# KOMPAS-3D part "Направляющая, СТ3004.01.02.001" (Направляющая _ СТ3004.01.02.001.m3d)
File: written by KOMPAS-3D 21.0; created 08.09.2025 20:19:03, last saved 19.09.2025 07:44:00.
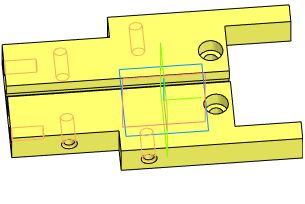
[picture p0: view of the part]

Document properties: Полное имя файла: C:\Users\Lutik\Yandex.Disk\Документы\Новая папка\Стапель №2\Стапель _ СТ3004.00.00.000\Опора _ СТ3004.01.00.000\3D\Кронштейн _ СТ3004.01.02.000\Направляющая _ СТ3004.01.02.001.m3d

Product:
- Part/product: Направляющая  | designation СТ3004.01.02.001
    Материал: Сталь 45  ГОСТ 1050-2013 (density 7810 kg/m3)
    Масса: 1.713262
    Форматы листов документа: A3

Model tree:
1. Эскиз:1
2. Элемент выдавливания:1
     Расстояние 1 = 80; Расстояние 2 = 95
3. Эскиз:2  (with: Элемент выдавливания:1)
4. Элемент выдавливания:2
     Расстояние 2 = 20
5. Эскиз:3  (with: Элемент выдавливания:1)
6. Элемент выдавливания:3
     Расстояние 2 = 20
7. Эскиз:4  (with: Элемент выдавливания:1, Элемент выдавливания:3)
8. Элемент выдавливания:4
     Расстояние 2 = 10
9. Эскиз:6  (with: Элемент выдавливания:1)
10. ЛСК:2  (with: Плоскость XY, Плоскость ZX, Плоскость ZY, Ось X, Ось Y, Ось Z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)
     Ось X. Y = -1; Ось Y. X = 1; Ось Z. Z = 1; Координата X = 25; Координата Y = -95; Координата Z = 10; Точка начала. Х = 25; Точка начала. Y = -95; Точка начала. Z = 10
11. Эскиз:7
12. Элемент вращения:1
     Угол 1 = 360
13. Смещенная плоскость:1  (with: Элемент выдавливания:1)
     Расстояние = 0.923418
14. Условное изображение резьбы:1  (with: Элемент вращения:1)  (labels: 8x1,25)
     Длина резьбы = 19.0766; Шаг резьбы = 1.25; Номинальный диаметр резьбы = 8
15. Подгонка:1
16. Отверстие М8x20/1,6x45°
17. Эскиз:9  (with: Элемент выдавливания:1)
18. ЛСК:4  (with: Плоскость XY, Плоскость ZX, Плоскость ZY, Ось X, Ось Y, Ось Z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)
     Ось X. Y = -1; Ось Y. X = 1; Ось Z. Z = 1; Координата X = -25; Координата Y = -95; Координата Z = 10; Точка начала. Х = -25; Точка начала. Y = -95; Точка начала. Z = 10
19. Эскиз:10
20. Элемент вращения:2
     Угол 1 = 360
21. Смещенная плоскость:2  (with: Элемент выдавливания:1)
     Расстояние = 0.923418
22. Условное изображение резьбы:2  (with: Элемент вращения:2)  (labels: 8x1,25)
     Длина резьбы = 19.0766; Шаг резьбы = 1.25; Номинальный диаметр резьбы = 8
23. Подгонка:2
24. Отверстие М8x20/1,6x45° (1)
25. Эскиз:28  (with: Элемент выдавливания:2)
26. ЛСК:18  (with: Плоскость XY, Плоскость ZX, Плоскость ZY, Ось X, Ось Y, Ось Z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)
     Ось X. X = 1; Ось Y. Y = 1; Ось Z. Z = 1; Координата X = 35; Координата Y = -60; Координата Z = 10; Точка начала. Х = 35; Точка начала. Y = -60; Точка начала. Z = 10
27. Эскиз:29
28. Элемент вращения:7
     Угол 1 = 360
29. Смещенная плоскость:7  (with: Элемент выдавливания:2)
     Расстояние = 0.923418
30. Условное изображение резьбы:7  (with: Элемент вращения:7, Подгонка:1)  (labels: 8x1,25)
     Длина резьбы = 19.0766; Шаг резьбы = 1.25; Номинальный диаметр резьбы = 8
31. Отверстие М8x20/1,6x45° (2)
32. Эскиз:32  (with: Элемент выдавливания:2)
33. ЛСК:21  (with: Плоскость XY, Плоскость ZX, Плоскость ZY, Ось X, Ось Y, Ось Z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)
     Ось X. X = -1; Ось Y. Y = 1; Ось Z. Z = -1; Координата X = -35; Координата Y = -60; Координата Z = 10; Точка начала. Х = -35; Точка начала. Y = -60; Точка начала. Z = 10
34. Эскиз:33
35. Элемент вращения:8
     Угол 1 = 360
36. Смещенная плоскость:8  (with: Элемент выдавливания:2)
     Расстояние = 0.923418
37. Условное изображение резьбы:8  (with: Элемент вращения:8, Подгонка:2)  (labels: 8x1,25)
     Длина резьбы = 19.0766; Шаг резьбы = 1.25; Номинальный диаметр резьбы = 8
38. Отверстие М8x20/1,6x45° (3)
39. Эскиз:20  (with: Элемент выдавливания:1)
40. ЛСК:12  (with: Плоскость XY, Плоскость ZX, Плоскость ZY, Ось X, Ось Y, Ось Z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)
     Ось X. X = -1; Ось Y. Y = 1; Ось Z. Z = -1; Координата X = -50; Координата Y = -13; Координата Z = 10; Точка начала. Х = -50; Точка начала. Y = -13; Точка начала. Z = 10
41. Эскиз:21
42. Элемент вращения:5
     Угол 1 = 360
43. Смещенная плоскость:5  (with: Элемент выдавливания:1)
     Расстояние = 0.923418
44. Условное изображение резьбы:5  (with: Элемент вращения:5)  (labels: 8x1,25)
     Длина резьбы = 19.0766; Шаг резьбы = 1.25; Номинальный диаметр резьбы = 8
45. Подгонка:5
46. Отверстие М8x20/1,6x45° (4)
47. Эскиз:24  (with: Элемент выдавливания:1)
48. ЛСК:15  (with: Плоскость XY, Плоскость ZX, Плоскость ZY, Ось X, Ось Y, Ось Z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)
     Ось X. X = 1; Ось Y. Y = 1; Ось Z. Z = 1; Координата X = 50; Координата Y = -13; Координата Z = 10; Точка начала. Х = 50; Точка начала. Y = -13; Точка начала. Z = 10
49. Эскиз:25
50. Элемент вращения:6
     Угол 1 = 360
51. Смещенная плоскость:6  (with: Элемент выдавливания:1)
     Расстояние = 0.923418
52. Условное изображение резьбы:6  (with: Элемент вращения:6)  (labels: 8x1,25)
     Длина резьбы = 19.0766; Шаг резьбы = 1.25; Номинальный диаметр резьбы = 8
53. Подгонка:6
54. Отверстие М8x20/1,6x45° (5)  (labels: Сталь 45  ГОСТ 1050-2013)

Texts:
  KTE.LIST=LTWD36N5dmSErgwNQxupvb
  Edge1
  Edge2
  СТ3004.01.02.001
